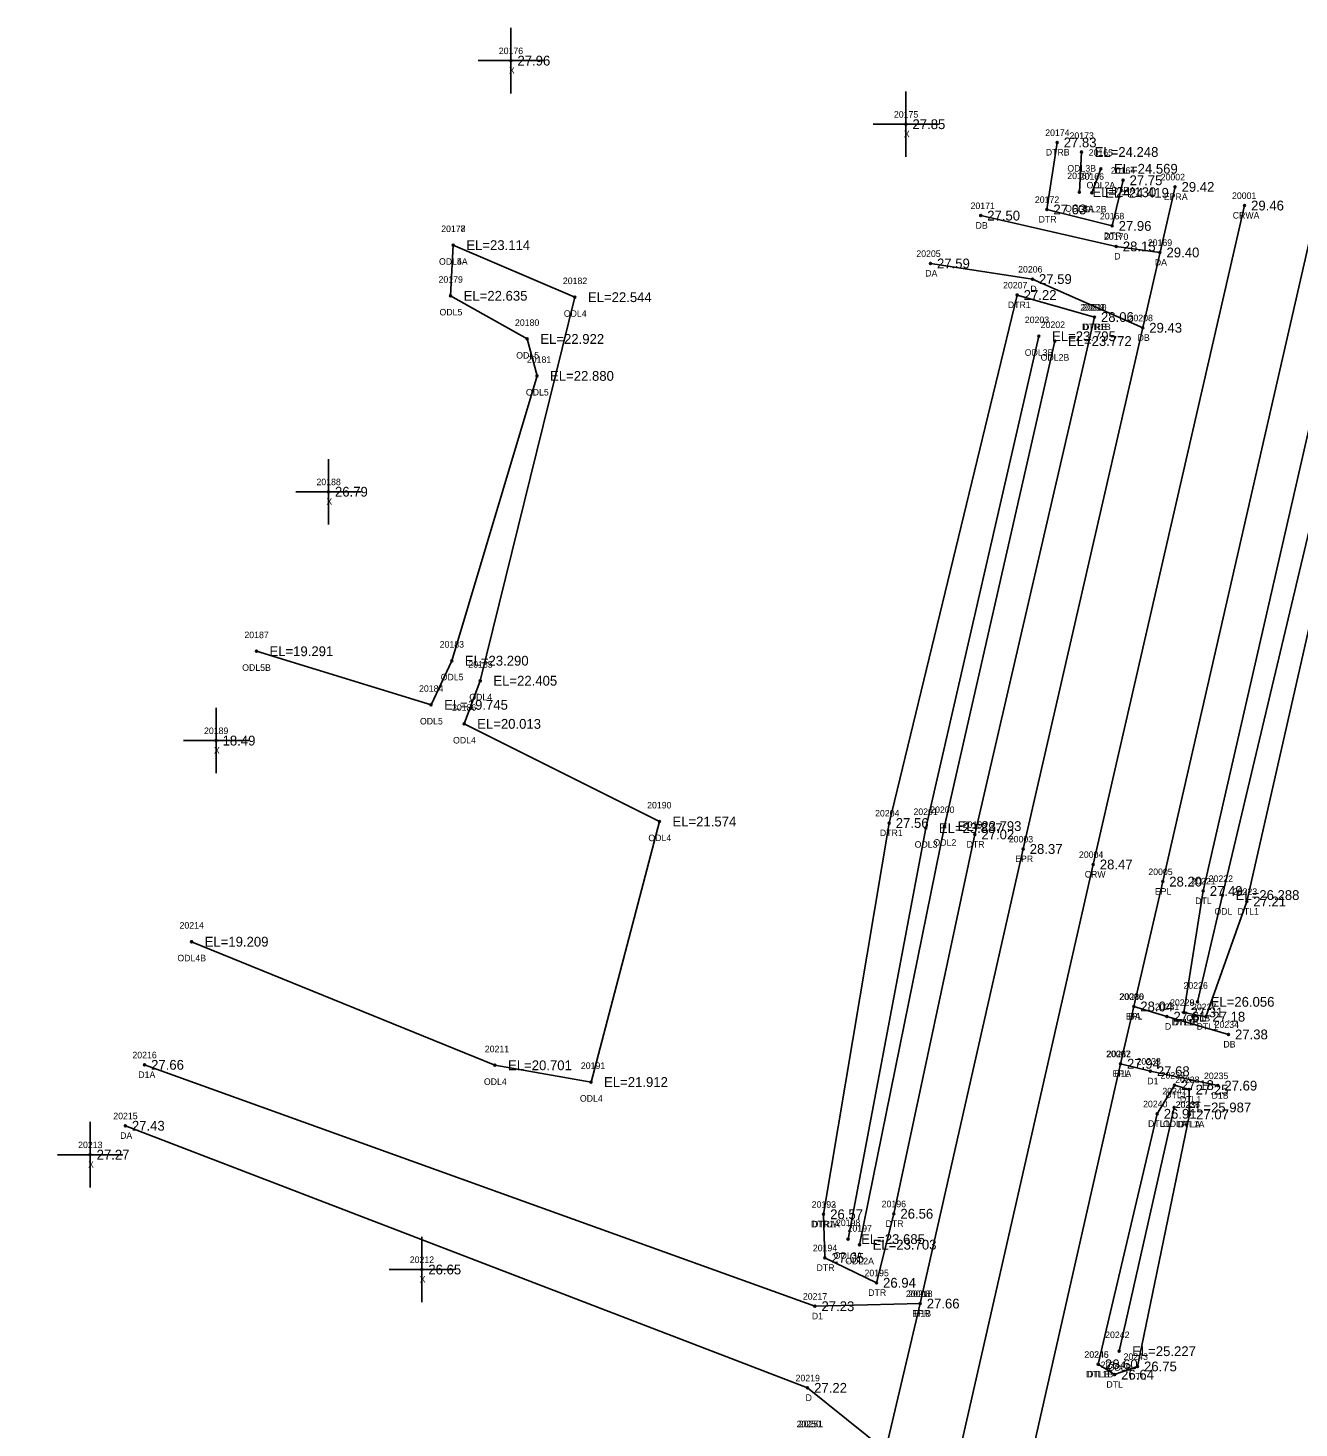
# Model space of a CAD drawing. Extents: x 2655177 to 2656219, y 761780 to 764748.
# Drawn here: x 2655866.3 to 2656060.7, y 764533.5 to 764747.6 of the extents above; entities that cross this region are included whole.
import ezdxf

# ---------------------------------------------------------------- set-up
doc = ezdxf.new("R2010")
doc.units = 0
for name, color, linetype in [('RD_DTM_BkLn1', 7, 'Continuous'), ('RD_EX_Driveway', 7, 'Continuous'), ('RD_EX_Driveway_txCode', 7, 'Continuous'), ('RD_EX_H2O', 7, 'Continuous'), ('RD_EX_H2O_txCode', 7, 'Continuous'), ('RD_EX_Misc', 7, 'Continuous'), ('RD_EX_Misc_txCode', 7, 'Continuous'), ('RD_EX_Road', 7, 'Continuous'), ('RD_EX_Road_txCode', 7, 'Continuous'), ('RD_EX_TX_Driveway_ELEV', 7, 'Continuous'), ('RD_EX_TX_H2O_ELEV', 7, 'Continuous'), ('RD_EX_TX_Misc_ELEV', 7, 'Continuous'), ('RD_EX_TX_Road_ELEV', 7, 'Continuous'), ('RD_HC_Survey_ELEV', 7, 'Continuous'), ('RD_HC_Survey_txCode', 7, 'Continuous'), ('RD_SMD_Locator', 7, 'Continuous')]:
    doc.layers.add(name, color=color, linetype=linetype)

msp = doc.modelspace()

# ---------------------------------------------------------------- linework, layer by layer
at = {"layer": 'RD_DTM_BkLn1'}
msp.add_lwpolyline([(2656052.36, 764720.46), (2656029.22, 764619.66), (2656007.41, 764523.97), (2655985.61, 764427.64), (2655963.53, 764330.64), (2655941.2, 764233.56), (2655920.06, 764141.06), (2655898.52, 764047.86), (2655877.71, 763954.88), (2655855.89, 763859.81), (2655834.07, 763763.97), (2655811.81, 763666.79), (2655790.48, 763573.22), (2655769.27, 763483.63), (2655747.64, 763389.32), (2655725.4, 763293.96), (2655721.51, 763275.9)], dxfattribs=at)
at = {"layer": 'RD_EX_Driveway'}
for points in [[(2656039.42, 764713.28), (2656032.74, 764714.2), (2656012, 764718.92)], [(2656004.32, 764711.6), (2656019.91, 764709.21), (2656036.78, 764701.76)], [(2656035.41, 764597.94), (2656040.48, 764596.39), (2656049.9, 764593.66)], [(2655884.12, 764589.01), (2655986.65, 764552.09), (2656002.75, 764552.49)], [(2656033.38, 764589.18), (2656037.95, 764588.04), (2656048.27, 764585.83)], [(2655881.18, 764579.69), (2655985.53, 764539.6), (2655997.43, 764530.02)]]:
    msp.add_lwpolyline(points, dxfattribs=at)
at = {"layer": 'RD_EX_H2O'}
for p, q in [((2656027.09, 764722.5), (2656027.42, 764728.65)), ((2656030.38, 764726.08), (2656029.02, 764722.4)), ((2656041.61, 764582.49), (2656033.16, 764545.21))]:
    msp.add_line(p, q, dxfattribs=at)
for points in [[(2656033.77, 764724.32), (2656032.1, 764717.34), (2656022.12, 764719.86), (2656023.7, 764730.11)], [(2656069.04, 764716.04), (2656046.04, 764615.61), (2656043.09, 764597.03)], [(2656072.8, 764715.16), (2656048.99, 764614.98), (2656045.17, 764598.65)], [(2655931.33, 764714.4), (2655949.93, 764706.44), (2655935.47, 764647.77), (2655932.99, 764641.17), (2655962.86, 764626.23), (2655952.4, 764586.38), (2655937.71, 764588.94), (2655891.31, 764607.85)], [(2655931.33, 764714.4), (2655930.92, 764706.65), (2655942.65, 764700.05), (2655944.14, 764694.4), (2655931.1, 764650.83), (2655927.93, 764644.08), (2655901.22, 764652.28)], [(2656075.55, 764714.51), (2656052.69, 764614), (2656046.44, 764596.38), (2656043.09, 764597.03)], [(2655987.98, 764566.15), (2655998.01, 764626), (2656017.58, 764706.77), (2656029.4, 764703.4)], [(2655987.98, 764566.15), (2655988.17, 764559.49), (2655996.07, 764555.67), (2655998.72, 764566.23), (2656011.11, 764624.25), (2656029.4, 764703.4)], [(2655991.71, 764562.35), (2656003.6, 764625.23), (2656020.91, 764700.47)], [(2655993.48, 764561.5), (2656006.47, 764625.53), (2656023.34, 764699.73)], [(2656043.95, 764581.43), (2656043.87, 764585.22), (2656041.64, 764585.91), (2656039, 764581.52), (2656029.99, 764543.2)], [(2656043.95, 764581.43), (2656035.98, 764542.87), (2656032.48, 764541.62), (2656029.99, 764543.2)]]:
    msp.add_lwpolyline(points, dxfattribs=at)
at = {"layer": 'RD_EX_Misc'}
for p, q in [((2655940.15, 764737.62), (2655940.15, 764747.62)), ((2655935.15, 764742.62), (2655945.15, 764742.62)), ((2656000.57, 764727.9), (2656000.57, 764737.9)), ((2655995.57, 764732.9), (2656005.57, 764732.9)), ((2655912.24, 764671.68), (2655912.24, 764681.68)), ((2655907.24, 764676.68), (2655917.24, 764676.68)), ((2655895.05, 764633.61), (2655895.05, 764643.61)), ((2655890.05, 764638.61), (2655900.05, 764638.61)), ((2655875.79, 764570.27), (2655875.79, 764580.27)), ((2655870.79, 764575.27), (2655880.79, 764575.27)), ((2655926.52, 764552.7), (2655926.52, 764562.7)), ((2655921.52, 764557.7), (2655931.52, 764557.7))]:
    msp.add_line(p, q, dxfattribs=at)
at = {"layer": 'RD_EX_Road'}
for points in [[(2656041.72, 764723.31), (2656018.5, 764622.03), (2656002.75, 764552.49), (2655997.43, 764530.02), (2655974.74, 764429.64), (2655952.97, 764333.57), (2655930.52, 764235.7), (2655909.18, 764142.93), (2655887.93, 764050.57), (2655866.91, 763957.26), (2655846.82, 763869.53), (2655845.21, 763862.22), (2655839.99, 763839.71), (2655823.38, 763766.66), (2655801.33, 763669.93), (2655780.03, 763576.53), (2655774.26, 763551.85), (2655771.37, 763539.86), (2655759.09, 763486.9), (2655736.94, 763391.72), (2655715.19, 763296.77), (2655711.35, 763278.45)], [(2656062.87, 764717.57), (2656039.84, 764617.04), (2656035.41, 764597.94), (2656033.38, 764589.18), (2656018.27, 764522.6), (2656017.22, 764517.64), (2656011.07, 764490.22), (2655996.52, 764425.63), (2655974.03, 764327.02), (2655960.71, 764269.34), (2655951.96, 764231.59), (2655930.84, 764138.62), (2655926.81, 764121.01)]]:
    msp.add_lwpolyline(points, dxfattribs=at)
at = {"layer": 'RD_SMD_Locator'}
for centre in [(2655940.15, 764742.62), (2656000.57, 764732.9), (2656023.7, 764730.11), (2656027.42, 764728.65), (2656030.38, 764726.08), (2656033.77, 764724.32), (2656041.72, 764723.31), (2656027.09, 764722.5), (2656029.02, 764722.4), (2656012, 764718.92), (2656022.12, 764719.86), (2656052.36, 764720.46), (2656032.1, 764717.34), (2655931.33, 764714.4), (2655931.33, 764714.4), (2656032.74, 764714.2), (2656039.42, 764713.28), (2656004.32, 764711.6), (2656019.91, 764709.21), (2655930.92, 764706.65), (2655949.93, 764706.44), (2656017.58, 764706.77), (2656029.4, 764703.4), (2656029.4, 764703.4), (2656036.78, 764701.76), (2655942.65, 764700.05), (2656020.91, 764700.47), (2656023.34, 764699.73), (2655944.14, 764694.4), (2655912.24, 764676.68), (2655901.22, 764652.28), (2655931.1, 764650.83), (2655935.47, 764647.77), (2655927.93, 764644.08), (2655932.99, 764641.17), (2655895.05, 764638.61), (2655962.86, 764626.23), (2655998.01, 764626), (2656003.6, 764625.23), (2656006.47, 764625.53), (2656011.11, 764624.25), (2656018.5, 764622.03), (2656029.22, 764619.66), (2656039.84, 764617.04), (2656046.04, 764615.61), (2656048.99, 764614.98), (2656052.69, 764614), (2655891.31, 764607.85), (2656035.41, 764597.94), (2656035.41, 764597.94), (2656043.09, 764597.03), (2656043.09, 764597.03), (2656045.17, 764598.65), (2656040.48, 764596.39), (2656046.44, 764596.38), (2656049.9, 764593.66), (2655884.12, 764589.01), (2655937.71, 764588.94), (2656033.38, 764589.18), (2656033.38, 764589.18), (2655952.4, 764586.38), (2656037.95, 764588.04), (2656041.64, 764585.91), (2656043.87, 764585.22), (2656048.27, 764585.83), (2656041.61, 764582.49), (2655881.18, 764579.69), (2656039, 764581.52), (2656043.95, 764581.43), (2656043.95, 764581.43), (2655875.79, 764575.27), (2655987.98, 764566.15), (2655987.98, 764566.15), (2655998.72, 764566.23), (2655991.71, 764562.35), (2655993.48, 764561.5), (2655988.17, 764559.49), (2655926.52, 764557.7), (2655996.07, 764555.67), (2655986.65, 764552.09), (2656002.75, 764552.49), (2656002.75, 764552.49), (2656033.16, 764545.21), (2656029.99, 764543.2), (2656029.99, 764543.2), (2656032.48, 764541.62), (2656035.98, 764542.87), (2655985.53, 764539.6)]:
    msp.add_circle(centre, 0.15, dxfattribs=at)

# ---------------------------------------------------------------- texts
at = {"layer": 'RD_EX_Driveway_txCode'}
for s, p in [('20171', (2656010.45, 764719.92)), ('DB', (2656011.22, 764716.92)), ('20170', (2656030.86, 764715.2)), ('20169', (2656037.56, 764714.28)), ('20205', (2656002.16, 764712.6)), ('D', (2656032.43, 764712.2)), ('DA', (2656003.52, 764709.6)), ('20206', (2656017.73, 764710.21)), ('DA', (2656038.63, 764711.28)), ('D', (2656019.6, 764707.21)), ('20208', (2656034.62, 764702.76)), ('DB', (2656036, 764699.76)), ('20230', (2656033.26, 764598.94)), ('20231', (2656038.65, 764597.39)), ('DA', (2656034.62, 764595.94)), ('D', (2656040.18, 764594.39)), ('20234', (2656047.78, 764594.66)), ('20216', (2655882.26, 764590.01)), ('20232', (2656031.26, 764590.18)), ('DB', (2656049.12, 764591.66)), ('20233', (2656035.83, 764589.04)), ('D1A', (2655883.16, 764587.01)), ('D1A', (2656032.42, 764587.18)), ('D1', (2656037.48, 764586.04)), ('20235', (2656046.15, 764586.83)), ('D1B', (2656047.32, 764583.83)), ('20215', (2655879.34, 764580.69)), ('DA', (2655880.38, 764577.69)), ('20218', (2656000.92, 764553.49)), ('20217', (2655984.81, 764553.09)), ('D1', (2655986.17, 764550.09)), ('D1B', (2656001.81, 764550.49)), ('20219', (2655983.69, 764540.6)), ('D', (2655985.22, 764537.6))]:
    msp.add_text(s, height=1, dxfattribs=at).set_placement(p)
at = {"layer": 'RD_EX_H2O_txCode'}
for s, p in [('20174', (2656021.87, 764731.11)), ('20173', (2656025.59, 764730.65)), ('DTRB', (2656021.96, 764728.11)), ('20165', (2656028.52, 764728.08)), ('20167', (2656025.24, 764724.5)), ('ODL3B', (2656025.26, 764725.65)), ('20164', (2656031.91, 764725.32)), ('20166', (2656027.14, 764724.4)), ('ODL2A', (2656028.19, 764723.08)), ('DTRA', (2656032.02, 764722.32)), ('20172', (2656020.29, 764720.86)), ('ODL3A', (2656024.91, 764719.5)), ('ODL2B', (2656026.86, 764719.4)), ('20168', (2656030.24, 764718.34)), ('20177', (2655929.49, 764716.4)), ('20178', (2655929.49, 764716.4)), ('DTR', (2656020.86, 764717.86)), ('DTR', (2656030.83, 764715.34)), ('ODL4A', (2655929.15, 764711.4)), ('ODL5A', (2655929.15, 764711.4)), ('20179', (2655929.08, 764708.65)), ('20182', (2655948.1, 764708.44)), ('20207', (2656015.42, 764707.77)), ('ODL5', (2655929.23, 764703.65)), ('ODL4', (2655948.24, 764703.44)), ('DTR1', (2656016.15, 764704.77)), ('20209', (2656027.24, 764704.4)), ('20210', (2656027.53, 764704.4)), ('20180', (2655940.77, 764702.05)), ('20203', (2656018.75, 764702.47)), ('20202', (2656021.18, 764701.73)), ('DTR1B', (2656027.5, 764701.4)), ('DTRB', (2656027.66, 764701.4)), ('ODL5', (2655940.96, 764697.05)), ('ODL3B', (2656018.74, 764697.47)), ('ODL2B', (2656021.17, 764696.73)), ('20181', (2655942.59, 764696.4)), ('ODL5', (2655942.44, 764691.4)), ('20187', (2655899.39, 764654.28)), ('20183', (2655929.26, 764652.83)), ('20185', (2655933.64, 764649.77)), ('ODL5B', (2655899.05, 764649.28)), ('ODL5', (2655929.41, 764647.83)), ('20184', (2655926.1, 764646.08)), ('20186', (2655931.14, 764643.17)), ('ODL4', (2655933.78, 764644.77)), ('ODL5', (2655926.24, 764641.08)), ('ODL4', (2655931.3, 764638.17)), ('20190', (2655960.99, 764628.23)), ('20204', (2655995.85, 764627)), ('20201', (2656001.72, 764627.23)), ('20200', (2656004.28, 764627.53)), ('DTR1', (2655996.58, 764624)), ('20199', (2656009.27, 764625.25)), ('ODL4', (2655961.17, 764623.23)), ('ODL3', (2656001.9, 764622.23)), ('ODL2', (2656004.78, 764622.53)), ('DTR', (2656009.84, 764622.25)), ('20221', (2656044.21, 764616.61)), ('20222', (2656046.87, 764616.98)), ('DTL', (2656044.8, 764613.61)), ('20223', (2656050.57, 764615)), ('ODL', (2656047.75, 764611.98)), ('DTL1', (2656051.28, 764612)), ('20214', (2655889.47, 764609.85)), ('ODL4B', (2655889.14, 764604.85)), ('20226', (2656043.02, 764600.65)), ('20228', (2656040.97, 764598.03)), ('20229', (2656040.97, 764598.03)), ('20227', (2656044.32, 764597.38)), ('DTL1B', (2656041.2, 764595.03)), ('DTLB', (2656041.37, 764595.03)), ('ODLB', (2656043.45, 764595.65)), ('DTL1', (2656045.03, 764594.38)), ('20211', (2655936.16, 764590.94)), ('20191', (2655950.85, 764588.38)), ('ODL4', (2655936.02, 764585.94)), ('20239', (2656039.52, 764586.91)), ('20238', (2656041.75, 764586.22)), ('ODL4', (2655950.7, 764583.38)), ('20241', (2656039.78, 764584.49)), ('DTL1', (2656040.23, 764583.91)), ('DTL1', (2656042.46, 764583.22)), ('20240', (2656036.84, 764582.52)), ('20236', (2656041.81, 764582.43)), ('20237', (2656041.84, 764582.43)), ('DTL1', (2656037.59, 764579.52)), ('ODLA', (2656039.88, 764579.49)), ('DTL1A', (2656042.06, 764579.43)), ('DTLA', (2656042.22, 764579.43)), ('20192', (2655986.15, 764567.15)), ('20193', (2655986.15, 764567.15)), ('20196', (2655996.86, 764567.23)), ('DTR1A', (2655986.06, 764564.15)), ('DTRA', (2655986.22, 764564.15)), ('20198', (2655989.87, 764564.35)), ('DTR', (2655997.45, 764564.23)), ('20197', (2655991.64, 764563.5)), ('20194', (2655986.33, 764560.49)), ('DTR', (2655986.9, 764557.49)), ('ODL3A', (2655989.52, 764559.35)), ('ODL2A', (2655991.29, 764558.5)), ('20195', (2655994.23, 764556.67)), ('DTR', (2655994.8, 764553.67)), ('20242', (2656031.04, 764547.21)), ('20246', (2656027.85, 764544.2)), ('20245', (2656027.88, 764544.2)), ('20244', (2656030.36, 764542.62)), ('20243', (2656033.86, 764543.87)), ('DTL1B', (2656028.11, 764541.2)), ('DTLB', (2656028.28, 764541.2)), ('ODLB', (2656031.44, 764542.21)), ('DTL', (2656034.73, 764540.87)), ('DTL', (2656031.23, 764539.62)), ('20250', (2655983.84, 764533.58)), ('20251', (2655984.16, 764533.58))]:
    msp.add_text(s, height=1, dxfattribs=at).set_placement(p)
at = {"layer": 'RD_EX_Misc_txCode'}
for s, p in [('20176', (2655938.3, 764743.62)), ('X', (2655939.84, 764740.62)), ('20175', (2655998.73, 764733.9)), ('X', (2656000.25, 764730.9)), ('20188', (2655910.41, 764677.68)), ('X', (2655911.93, 764674.68)), ('20189', (2655893.21, 764639.61)), ('X', (2655894.73, 764636.61)), ('20213', (2655873.96, 764576.27)), ('X', (2655875.48, 764573.27)), ('20212', (2655924.68, 764558.7)), ('X', (2655926.2, 764555.7))]:
    msp.add_text(s, height=1, dxfattribs=at).set_placement(p)
at = {"layer": 'RD_EX_Road_txCode'}
for s, p in [('20002', (2656039.53, 764724.31)), ('EPRA', (2656040.01, 764721.31)), ('20003', (2656016.3, 764623.03)), ('EPR', (2656017.27, 764620.03)), ('20005', (2656037.64, 764618.04)), ('EPL', (2656038.63, 764615.04)), ('20006', (2656033.19, 764598.94)), ('EPL', (2656034.21, 764595.94)), ('20007', (2656031.18, 764590.18)), ('EPL', (2656032.17, 764587.18)), ('20008', (2656000.56, 764553.49)), ('EPR', (2656001.52, 764550.49))]:
    msp.add_text(s, height=1, dxfattribs=at).set_placement(p)
at = {"layer": 'RD_EX_TX_Driveway_ELEV'}
for s, p in [('27.50', (2656013, 764718.17)), ('28.15', (2656033.74, 764713.45)), ('29.40', (2656040.42, 764712.53)), ('27.59', (2656005.32, 764710.85)), ('27.59', (2656020.91, 764708.46)), ('29.43', (2656037.78, 764701.01)), ('28.04', (2656036.41, 764597.19)), ('27.61', (2656041.48, 764595.64)), ('27.38', (2656050.9, 764592.91)), ('27.66', (2655885.12, 764588.26)), ('27.94', (2656034.38, 764588.43)), ('27.68', (2656038.95, 764587.29)), ('27.69', (2656049.27, 764585.08)), ('27.43', (2655882.18, 764578.94)), ('27.23', (2655987.65, 764551.34)), ('27.66', (2656003.75, 764551.74)), ('27.22', (2655986.53, 764538.85))]:
    msp.add_text(s, height=1.5, dxfattribs=at).set_placement(p)
at = {"layer": 'RD_EX_TX_H2O_ELEV'}
for s, p in [('27.83', (2656024.7, 764729.36)), ('EL=24.248', (2656029.42, 764727.9)), ('EL=24.569', (2656032.38, 764725.33)), ('27.75', (2656034.77, 764723.57)), ('EL=24.130', (2656029.09, 764721.75)), ('EL=24.419', (2656031.02, 764721.65)), ('27.63', (2656023.12, 764719.11)), ('27.96', (2656033.1, 764716.59)), ('EL=23.114', (2655933.33, 764713.65)), ('EL=23.114', (2655933.33, 764713.65)), ('EL=22.635', (2655932.92, 764705.9)), ('EL=22.544', (2655951.93, 764705.69)), ('27.22', (2656018.58, 764706.02)), ('28.06', (2656030.4, 764702.65)), ('28.06', (2656030.4, 764702.65)), ('EL=22.922', (2655944.65, 764699.3)), ('EL=23.795', (2656022.91, 764699.72)), ('EL=23.772', (2656025.34, 764698.98)), ('EL=22.880', (2655946.14, 764693.65)), ('EL=19.291', (2655903.22, 764651.53)), ('EL=23.290', (2655933.1, 764650.08)), ('EL=22.405', (2655937.47, 764647.02)), ('EL=19.745', (2655929.93, 764643.33)), ('EL=20.013', (2655934.99, 764640.42)), ('EL=21.574', (2655964.86, 764625.48)), ('27.56', (2655999.01, 764625.25)), ('EL=23.887', (2656005.6, 764624.48)), ('EL=23.793', (2656008.47, 764624.78)), ('27.02', (2656012.11, 764623.5)), ('27.49', (2656047.04, 764614.86)), ('EL=26.288', (2656050.99, 764614.23)), ('27.21', (2656053.69, 764613.25)), ('EL=19.209', (2655893.31, 764607.1)), ('EL=26.056', (2656047.17, 764597.9)), ('27.31', (2656044.09, 764596.28)), ('27.31', (2656044.09, 764596.28)), ('27.18', (2656047.44, 764595.63)), ('EL=20.701', (2655939.71, 764588.19)), ('EL=21.912', (2655954.4, 764585.63)), ('27.18', (2656042.64, 764585.16)), ('27.25', (2656044.87, 764584.47)), ('26.91', (2656040, 764580.77)), ('EL=25.987', (2656043.61, 764581.74)), ('27.07', (2656044.95, 764580.68)), ('27.07', (2656044.95, 764580.68)), ('26.56', (2655999.72, 764565.48)), ('26.57', (2655988.98, 764565.4)), ('26.57', (2655988.98, 764565.4)), ('EL=23.685', (2655993.71, 764561.6)), ('EL=23.703', (2655995.48, 764560.75)), ('27.05', (2655989.17, 764558.74)), ('26.94', (2655997.07, 764554.92)), ('EL=25.227', (2656035.16, 764544.46)), ('26.60', (2656030.99, 764542.45)), ('26.60', (2656030.99, 764542.45)), ('26.75', (2656036.98, 764542.12)), ('26.64', (2656033.48, 764540.87))]:
    msp.add_text(s, height=1.5, dxfattribs=at).set_placement(p)
at = {"layer": 'RD_EX_TX_Misc_ELEV'}
for s, p in [('27.96', (2655941.15, 764741.87)), ('27.85', (2656001.57, 764732.15)), ('26.79', (2655913.24, 764675.93)), ('18.49', (2655896.05, 764637.86)), ('27.27', (2655876.79, 764574.52)), ('26.65', (2655927.52, 764556.95))]:
    msp.add_text(s, height=1.5, dxfattribs=at).set_placement(p)
at = {"layer": 'RD_EX_TX_Road_ELEV'}
for s, p in [('29.42', (2656042.72, 764722.56)), ('28.37', (2656019.5, 764621.28)), ('28.20', (2656040.84, 764616.29)), ('28.04', (2656036.41, 764597.19)), ('27.94', (2656034.38, 764588.43)), ('27.66', (2656003.75, 764551.74))]:
    msp.add_text(s, height=1.5, dxfattribs=at).set_placement(p)
at = {"layer": 'RD_HC_Survey_ELEV'}
for s, p in [('29.46', (2656053.36, 764719.71)), ('28.47', (2656030.22, 764618.91))]:
    msp.add_text(s, height=1.5, dxfattribs=at).set_placement(p)
at = {"layer": 'RD_HC_Survey_txCode'}
for s, p in [('20001', (2656050.44, 764721.46)), ('CRWA', (2656050.55, 764718.46)), ('20004', (2656027.03, 764620.66)), ('CRW', (2656027.91, 764617.66))]:
    msp.add_text(s, height=1, dxfattribs=at).set_placement(p)

doc.saveas('drawing.dxf')
